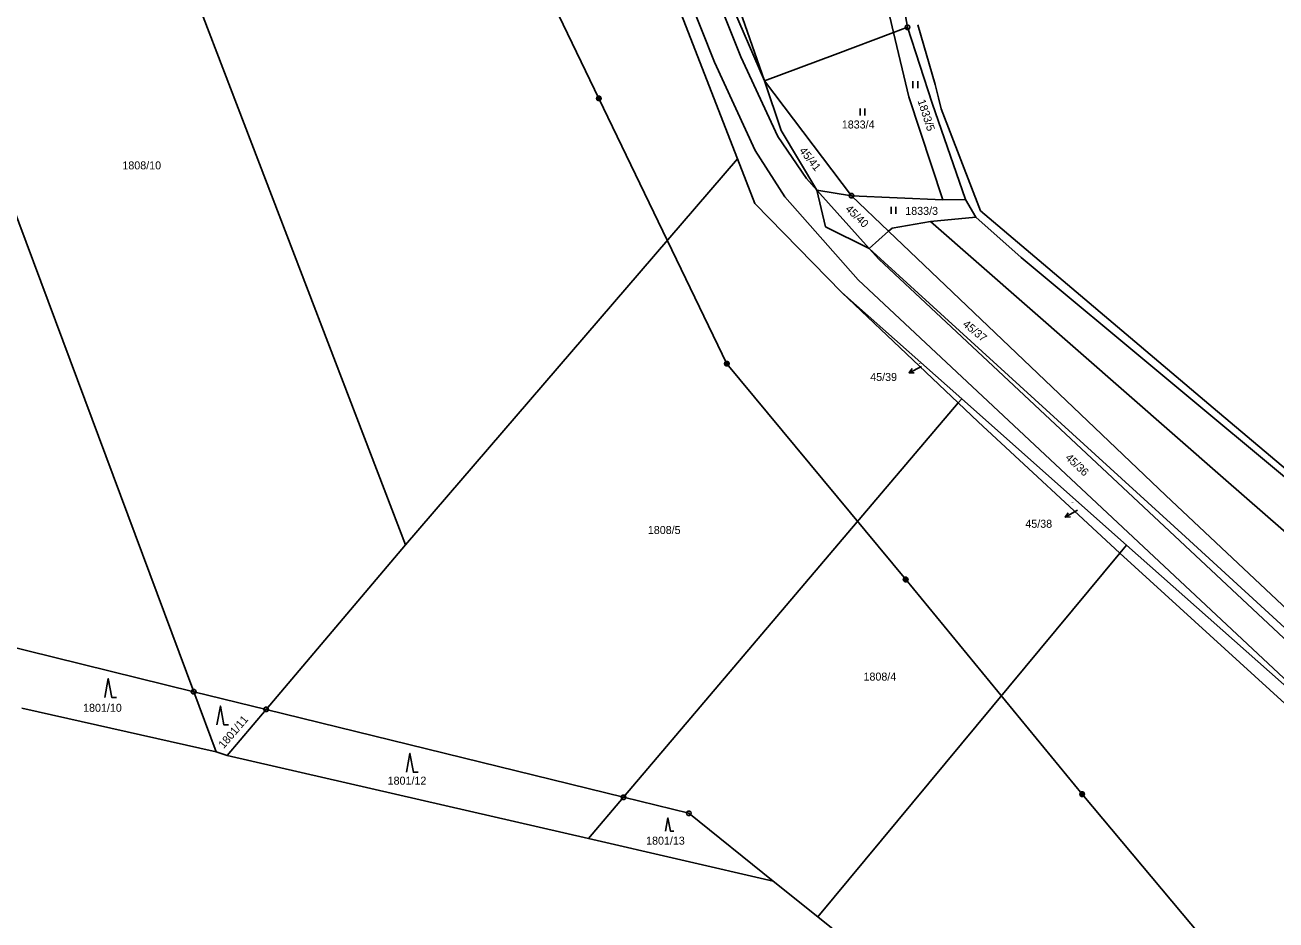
# Model space of a CAD drawing. Extents: x -609861 to -605046, y -1120287 to -1116307.
# Drawn here: x -608867.9 to -608602.1, y -1117246.3 to -1117056.1 of the extents above; entities that cross this region are included whole.
import ezdxf

# ---------------------------------------------------------------- set-up
doc = ezdxf.new("R2010")
doc.units = 0
for name, color, linetype in [('Vrstva 1', 7, 'Continuous'), ('Vrstva 2', 7, 'Continuous'), ('Vrstva 3', 7, 'Continuous'), ('Vrstva 4', 7, 'Continuous'), ('Vrstva 6', 7, 'Continuous'), ('Vrstva 7', 7, 'Continuous'), ('Vrstva 8', 7, 'Continuous')]:
    doc.layers.add(name, color=color, linetype=linetype)

msp = doc.modelspace()

# ---------------------------------------------------------------- linework, layer by layer
at = {"layer": 'Vrstva 1'}
for p, q in [((-608717.66, -1117081.65), (-608757.97, -1116977.84)), ((-608787, -1117166.57), (-608857.29, -1116983.01)), ((-608745.28, -1116987.83), (-608710.81, -1117067.93)), ((-608906.23, -1116998.7), (-608832.02, -1117197.78)), ((-608683.35, -1117057.67), (-608689.67, -1117030.74)), ((-608685.15, -1117029.21), (-608680.39, -1117056.57)), ((-608720.16, -1117041.02), (-608710.81, -1117067.93)), ((-608683.35, -1117057.67), (-608695.8, -1117062.33)), ((-608680.39, -1117056.57), (-608683.35, -1117057.67)), ((-608680.13, -1117071.36), (-608683.35, -1117057.67)), ((-608680.39, -1117056.57), (-608675.14, -1117072.71)), ((-608678.22, -1117056.08), (-608674.52, -1117068.7)), ((-608695.8, -1117062.33), (-608710.81, -1117067.93)), ((-608707.25, -1117078.52), (-608710.81, -1117067.93)), ((-608710.81, -1117067.93), (-608692.31, -1117092.37)), ((-608674.52, -1117068.7), (-608673.83, -1117071.59)), ((-608672.92, -1117093.21), (-608680.13, -1117071.36)), ((-608675.14, -1117072.71), (-608668.05, -1117093.17)), ((-608673.83, -1117071.59), (-608673.27, -1117073.92)), ((-608673.27, -1117073.92), (-608664.92, -1117095.58)), ((-608699.64, -1117091.19), (-608707.25, -1117078.52)), ((-608716.53, -1117084.53), (-608717.66, -1117081.65)), ((-608787, -1117166.57), (-608716.53, -1117084.53)), ((-608712.8, -1117094), (-608716.53, -1117084.53)), ((-608692.31, -1117092.37), (-608699.64, -1117091.19)), ((-608699.64, -1117091.19), (-608697.81, -1117098.99)), ((-608692.31, -1117092.37), (-608672.92, -1117093.21)), ((-608692.31, -1117092.37), (-608684.42, -1117099.89)), ((-608694.32, -1117112.92), (-608712.8, -1117094)), ((-608672.92, -1117093.21), (-608668.05, -1117093.17)), ((-608668.05, -1117093.17), (-608665.91, -1117096.95)), ((-608675.49, -1117097.82), (-608683.69, -1117099.24)), ((-608675.49, -1117097.82), (-608665.91, -1117096.95)), ((-608613.32, -1117152.36), (-608675.49, -1117097.82)), ((-608665.91, -1117096.95), (-608656.25, -1117105.49)), ((-608664.92, -1117095.58), (-608615.46, -1117137.42)), ((-608697.81, -1117098.99), (-608688.54, -1117103.57)), ((-608684.42, -1117099.89), (-608688.54, -1117103.57)), ((-608683.69, -1117099.24), (-608684.42, -1117099.89)), ((-608684.42, -1117099.89), (-608625.51, -1117156.09)), ((-608688.54, -1117103.57), (-608621.35, -1117164.85)), ((-608656.25, -1117105.49), (-608592.02, -1117159.08)), ((-608668.87, -1117135.51), (-608694.32, -1117112.92)), ((-608669.62, -1117136.39), (-608694.32, -1117112.92)), ((-608669.62, -1117136.39), (-608740.72, -1117220.22)), ((-608668.87, -1117135.51), (-608669.62, -1117136.39)), ((-608665.41, -1117140.39), (-608669.62, -1117136.39)), ((-608633.89, -1117166.62), (-608668.87, -1117135.51)), ((-608615.46, -1117137.42), (-608591.29, -1117157.86)), ((-608635.28, -1117168.31), (-608665.41, -1117140.39)), ((-608548.08, -1117209.43), (-608613.32, -1117152.36)), ((-608625.51, -1117156.09), (-608590.8, -1117188.81)), ((-608816.63, -1117201.56), (-608787, -1117166.57)), ((-608635.28, -1117168.31), (-608633.89, -1117166.62)), ((-608572.58, -1117221.03), (-608633.89, -1117166.62)), ((-608621.35, -1117164.85), (-608574.9, -1117207.53)), ((-608635.28, -1117168.31), (-608699.42, -1117245.66)), ((-608600.24, -1117200.31), (-608635.28, -1117168.31)), ((-608873.65, -1117187.55), (-608832.02, -1117197.78)), ((-608832.02, -1117197.78), (-608816.63, -1117201.56)), ((-608832.02, -1117197.78), (-608827.26, -1117210.55)), ((-608868.51, -1117201.29), (-608827.26, -1117210.55)), ((-608824.91, -1117211.34), (-608816.63, -1117201.56)), ((-608816.63, -1117201.56), (-608740.72, -1117220.22)), ((-608827.26, -1117210.55), (-608824.91, -1117211.34)), ((-608824.91, -1117211.34), (-608748.13, -1117228.96)), ((-608740.72, -1117220.22), (-608748.13, -1117228.96)), ((-608740.72, -1117220.22), (-608726.84, -1117223.63)), ((-608726.84, -1117223.63), (-608708.91, -1117238.03)), ((-608748.13, -1117228.96), (-608708.91, -1117238.03)), ((-608708.91, -1117238.03), (-608699.42, -1117245.66)), ((-608699.42, -1117245.66), (-608633.95, -1117298.24))]:
    msp.add_line(p, q, dxfattribs=at)
at = {"layer": 'Vrstva 3'}
for p, q in [((-608679.24, -1117068.03), (-608679.24, -1117069.53)), ((-608678.24, -1117069.53), (-608678.24, -1117068.03)), ((-608690.46, -1117073.83), (-608690.46, -1117075.33)), ((-608689.46, -1117075.33), (-608689.46, -1117073.83)), ((-608683.89, -1117094.7), (-608683.89, -1117096.2)), ((-608682.89, -1117096.2), (-608682.89, -1117094.7))]:
    msp.add_line(p, q, dxfattribs=at)
for points in [[(-608850.93, -1117198.98), (-608850.18, -1117194.98), (-608849.43, -1117198.98), (-608848.43, -1117198.98)], [(-608827.1, -1117204.84), (-608826.35, -1117200.84), (-608825.6, -1117204.84), (-608824.6, -1117204.84)], [(-608786.84, -1117214.89), (-608786.09, -1117210.89), (-608785.34, -1117214.89), (-608784.34, -1117214.89)], [(-608731.815, -1117227.4), (-608731.29, -1117224.6), (-608730.765, -1117227.4), (-608730.065, -1117227.4)]]:
    msp.add_lwpolyline(points, dxfattribs=at)
at = {"layer": 'Vrstva 4'}
for p, q in [((-608721.43, -1117063.98), (-608834.12, -1116778.22)), ((-608812.32, -1116818.33), (-608715.82, -1117062.88)), ((-608715.82, -1117062.88), (-608707.92, -1117079.77)), ((-608712.75, -1117082.77), (-608721.43, -1117063.98)), ((-608707.92, -1117079.77), (-608701.85, -1117088.73)), ((-608706.49, -1117092.63), (-608712.75, -1117082.77)), ((-608701.85, -1117088.73), (-608699.64, -1117091.19)), ((-608690.9, -1117110.24), (-608706.49, -1117092.63)), ((-608699.64, -1117091.19), (-608688.54, -1117103.57)), ((-608688.54, -1117103.57), (-608686.51, -1117105.83)), ((-608686.51, -1117105.83), (-608406.86, -1117367.8)), ((-608572.58, -1117221.03), (-608690.9, -1117110.24))]:
    msp.add_line(p, q, dxfattribs=at)
at = {"layer": 'Vrstva 6'}
for p, q in [((-608745.96, -1117071.69), (-608776.77, -1117007.78)), ((-608718.78, -1117128.07), (-608745.96, -1117071.69)), ((-608680.79, -1117173.95), (-608718.78, -1117128.07)), ((-608643.31, -1117219.57), (-608680.79, -1117173.95)), ((-608604.03, -1117266.42), (-608643.31, -1117219.57))]:
    msp.add_line(p, q, dxfattribs=at)
for points in [[(-608746.11, -1117071.21), (-608745.8, -1117071.21), (-608745.55, -1117071.39), (-608745.45, -1117071.68), (-608745.55, -1117071.97), (-608745.8, -1117072.15), (-608746.11, -1117072.15), (-608746.36, -1117071.97), (-608746.46, -1117071.68), (-608746.36, -1117071.39), (-608746.11, -1117071.21), (-608746.08, -1117071.25), (-608745.84, -1117071.25), (-608745.68, -1117071.33), (-608746.24, -1117071.33), (-608746.32, -1117071.41), (-608745.6, -1117071.41), (-608745.6, -1117071.49), (-608746.32, -1117071.49), (-608746.36, -1117071.57), (-608745.56, -1117071.57), (-608745.52, -1117071.65), (-608746.4, -1117071.65), (-608746.4, -1117071.73), (-608745.52, -1117071.73), (-608745.55, -1117071.81), (-608746.36, -1117071.81), (-608746.35, -1117071.89), (-608745.54, -1117071.89), (-608745.59, -1117071.97), (-608746.31, -1117071.97), (-608746.23, -1117072.05), (-608745.67, -1117072.05), (-608745.78, -1117072.13), (-608746.12, -1117072.13)], [(-608718.93, -1117127.59), (-608718.62, -1117127.59), (-608718.37, -1117127.77), (-608718.27, -1117128.06), (-608718.37, -1117128.35), (-608718.62, -1117128.53), (-608718.93, -1117128.53), (-608719.18, -1117128.35), (-608719.28, -1117128.06), (-608719.18, -1117127.77), (-608718.93, -1117127.59), (-608718.9, -1117127.63), (-608718.66, -1117127.63), (-608718.5, -1117127.71), (-608719.06, -1117127.71), (-608719.14, -1117127.79), (-608718.42, -1117127.79), (-608718.42, -1117127.87), (-608719.14, -1117127.87), (-608719.18, -1117127.95), (-608718.38, -1117127.95), (-608718.34, -1117128.03), (-608719.22, -1117128.03), (-608719.22, -1117128.11), (-608718.34, -1117128.11), (-608718.37, -1117128.19), (-608719.18, -1117128.19), (-608719.17, -1117128.27), (-608718.36, -1117128.27), (-608718.41, -1117128.35), (-608719.13, -1117128.35), (-608719.05, -1117128.43), (-608718.49, -1117128.43), (-608718.6, -1117128.51), (-608718.94, -1117128.51)], [(-608680.94, -1117173.47), (-608680.63, -1117173.47), (-608680.38, -1117173.65), (-608680.28, -1117173.94), (-608680.38, -1117174.23), (-608680.63, -1117174.41), (-608680.94, -1117174.41), (-608681.19, -1117174.23), (-608681.29, -1117173.94), (-608681.19, -1117173.65), (-608680.94, -1117173.47), (-608680.91, -1117173.51), (-608680.67, -1117173.51), (-608680.51, -1117173.59), (-608681.07, -1117173.59), (-608681.15, -1117173.67), (-608680.43, -1117173.67), (-608680.43, -1117173.75), (-608681.15, -1117173.75), (-608681.19, -1117173.83), (-608680.39, -1117173.83), (-608680.35, -1117173.91), (-608681.23, -1117173.91), (-608681.23, -1117173.99), (-608680.35, -1117173.99), (-608680.38, -1117174.07), (-608681.19, -1117174.07), (-608681.18, -1117174.15), (-608680.37, -1117174.15), (-608680.42, -1117174.23), (-608681.14, -1117174.23), (-608681.06, -1117174.31), (-608680.5, -1117174.31), (-608680.61, -1117174.39), (-608680.95, -1117174.39)], [(-608643.46, -1117219.09), (-608643.15, -1117219.09), (-608642.9, -1117219.27), (-608642.8, -1117219.56), (-608642.9, -1117219.85), (-608643.15, -1117220.03), (-608643.46, -1117220.03), (-608643.71, -1117219.85), (-608643.81, -1117219.56), (-608643.71, -1117219.27), (-608643.46, -1117219.09), (-608643.43, -1117219.13), (-608643.19, -1117219.13), (-608643.03, -1117219.21), (-608643.59, -1117219.21), (-608643.67, -1117219.29), (-608642.95, -1117219.29), (-608642.95, -1117219.37), (-608643.67, -1117219.37), (-608643.71, -1117219.45), (-608642.91, -1117219.45), (-608642.87, -1117219.53), (-608643.75, -1117219.53), (-608643.75, -1117219.61), (-608642.87, -1117219.61), (-608642.9, -1117219.69), (-608643.71, -1117219.69), (-608643.7, -1117219.77), (-608642.89, -1117219.77), (-608642.94, -1117219.85), (-608643.66, -1117219.85), (-608643.58, -1117219.93), (-608643.02, -1117219.93), (-608643.13, -1117220.01), (-608643.47, -1117220.01)]]:
    msp.add_lwpolyline(points, dxfattribs=at)
at = {"layer": 'Vrstva 7'}
for p, q in [((-608680.078, -1117130.003), (-608677.41, -1117128.63)), ((-608646.894, -1117160.72), (-608644.32, -1117159.18))]:
    msp.add_line(p, q, dxfattribs=at)
for points in [[(-608678.96, -1117129.99), (-608680.078, -1117130.003), (-608679.417, -1117129.1)], [(-608645.78, -1117160.636), (-608646.894, -1117160.72), (-608646.293, -1117159.778)]]:
    msp.add_lwpolyline(points, dxfattribs=at)
at = {"layer": 'Vrstva 8'}
for p, q in [((-608680.51, -1117056.57), (-608680.27, -1117056.57)), ((-608692.43, -1117092.37), (-608692.19, -1117092.37)), ((-608832.14, -1117197.78), (-608831.9, -1117197.78)), ((-608816.75, -1117201.56), (-608816.51, -1117201.56)), ((-608740.84, -1117220.22), (-608740.6, -1117220.22)), ((-608726.96, -1117223.63), (-608726.72, -1117223.63))]:
    msp.add_line(p, q, dxfattribs=at)
for points in [[(-608680.24, -1117056.09), (-608679.99, -1117056.27), (-608679.89, -1117056.56), (-608679.99, -1117056.85), (-608680.24, -1117057.03), (-608680.55, -1117057.03), (-608680.8, -1117056.85), (-608680.9, -1117056.56), (-608680.8, -1117056.27), (-608680.55, -1117056.09)], [(-608692.16, -1117091.89), (-608691.91, -1117092.07), (-608691.81, -1117092.36), (-608691.91, -1117092.65), (-608692.16, -1117092.83), (-608692.47, -1117092.83), (-608692.72, -1117092.65), (-608692.82, -1117092.36), (-608692.72, -1117092.07), (-608692.47, -1117091.89)], [(-608831.87, -1117197.3), (-608831.62, -1117197.48), (-608831.52, -1117197.77), (-608831.62, -1117198.06), (-608831.87, -1117198.24), (-608832.18, -1117198.24), (-608832.43, -1117198.06), (-608832.53, -1117197.77), (-608832.43, -1117197.48), (-608832.18, -1117197.3)], [(-608816.48, -1117201.08), (-608816.23, -1117201.26), (-608816.13, -1117201.55), (-608816.23, -1117201.84), (-608816.48, -1117202.02), (-608816.79, -1117202.02), (-608817.04, -1117201.84), (-608817.14, -1117201.55), (-608817.04, -1117201.26), (-608816.79, -1117201.08)], [(-608740.57, -1117219.74), (-608740.32, -1117219.92), (-608740.22, -1117220.21), (-608740.32, -1117220.5), (-608740.57, -1117220.68), (-608740.88, -1117220.68), (-608741.13, -1117220.5), (-608741.23, -1117220.21), (-608741.13, -1117219.92), (-608740.88, -1117219.74)], [(-608726.69, -1117223.15), (-608726.44, -1117223.33), (-608726.34, -1117223.62), (-608726.44, -1117223.91), (-608726.69, -1117224.09), (-608727, -1117224.09), (-608727.25, -1117223.91), (-608727.35, -1117223.62), (-608727.25, -1117223.33), (-608727, -1117223.15)]]:
    msp.add_lwpolyline(points, close=True, dxfattribs=at)

# ---------------------------------------------------------------- texts
at = {"layer": 'Vrstva 2'}
for s, rotation, p in [('1833/5', 288.02588, (-608678.288, -1117072.193)), ('45/41', 308.70966, (-608703.512, -1117082.865)), ('45/40', 315.87163, (-608693.74, -1117095.345)), ('45/37', 320.398, (-608668.817, -1117119.931)), ('45/36', 316.78836, (-608647.017, -1117148.223)), ('1801/11', 49.50355, (-608825.645, -1117209.991))]:
    msp.add_text(s, height=1.7, rotation=rotation, dxfattribs=at).set_placement(p)
for s, height, p in [('1833/4', 1.7, (-608694.357, -1117078.08)), ('1808/10', 1.7, (-608847.167, -1117086.77)), ('1833/3', 1.7, (-608680.877, -1117096.44)), ('45/39', 0.2, (-608678.042, -1117128.13)), ('45/38', 0.2, (-608645.692, -1117157.66)), ('1808/5', 1.7, (-608735.557, -1117164.26)), ('1808/4', 1.7, (-608689.747, -1117195.42)), ('1801/10', 1.7, (-608855.517, -1117202.05)), ('1801/12', 1.7, (-608790.827, -1117217.54)), ('1801/13', 1.7, (-608735.927, -1117230.29))]:
    msp.add_text(s, height=height, dxfattribs=at).set_placement(p)
at = {"layer": 'Vrstva 7'}
for s, p in [('45/39', (-608688.322, -1117131.74)), ('45/38', (-608655.372, -1117162.94))]:
    msp.add_text(s, height=1.7, dxfattribs=at).set_placement(p)

doc.saveas('drawing.dxf')
